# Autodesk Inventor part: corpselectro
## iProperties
Created: 2007-07
Part Number: corpselectro
Document SubType Name: Modeling
Designer: EF
Density: 1 g/cm^3
Author: EF
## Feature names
1. Base1
2. Extrusion1
3. Extrusion2
4. Extrusion3
